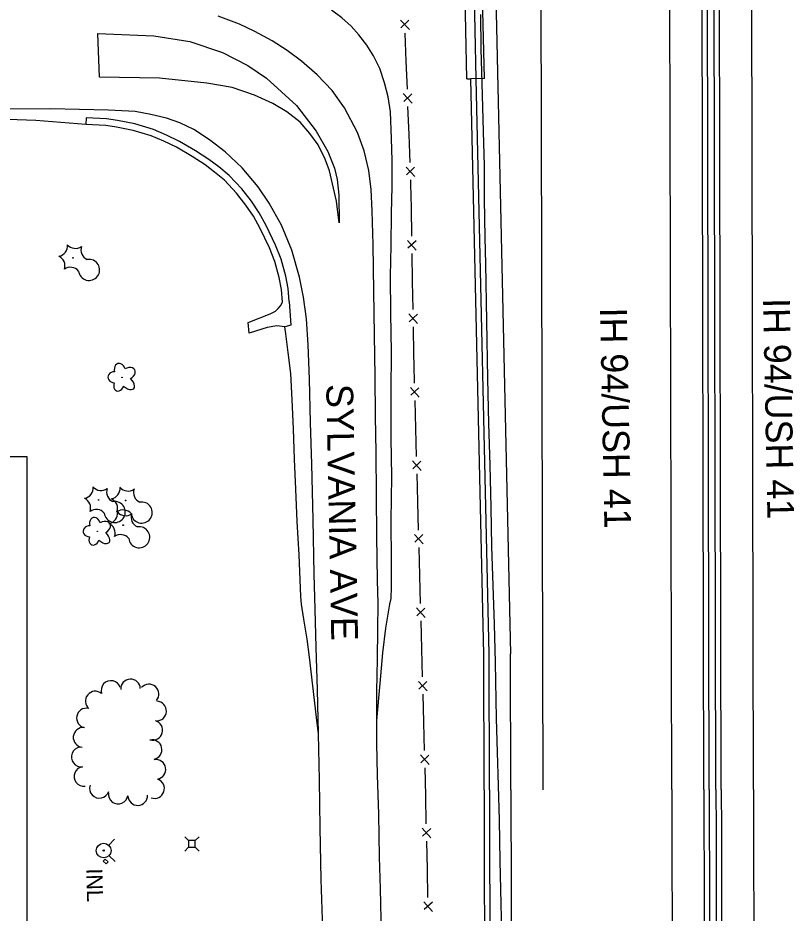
# Model space of a CAD drawing. Extents: x 588843 to 2552415, y 180129 to 269402.
# Drawn here: x 593759.6 to 594049.2, y 183657 to 183991.2 of the extents above; entities that cross this region are included whole.
import ezdxf

# ---------------------------------------------------------------- set-up
doc = ezdxf.new("R2010")
doc.units = 0
for name, color, linetype in [('Default', 7, 'Continuous'), ('E_BLD', 7, 'Continuous'), ('E_DRN', 7, 'Continuous'), ('E_DRN_Text', 7, 'Continuous'), ('E_FEN_P', 7, 'Continuous'), ('E_LAND_TreeLine_P', 7, 'Continuous'), ('E_LAND_Vegetation', 7, 'Continuous'), ('E_RDWY', 7, 'Continuous'), ('E_RDWY_C_and_G', 7, 'Continuous'), ('E_RDWY_Gravel', 7, 'Continuous'), ('E_RDWY_Text', 7, 'Continuous'), ('E_UTL_AG_Bold', 7, 'Continuous'), ('E_UTL_WHydrant', 7, 'Continuous'), ('P_BMGRD', 7, 'Continuous'), ('P_RDWY_BarrierConc', 7, 'Continuous'), ('P_RDWY_PavtEdge', 7, 'Continuous'), ('P_RDWY_ShldPaved', 7, 'Continuous')]:
    doc.layers.add(name, color=color, linetype=linetype)

# ---------------------------------------------------------------- blocks, each defined once
blk = doc.blocks.new('CTRE')
at = {"layer": 'Default'}
blk.add_circle((0, 0), 0.223, dxfattribs=at)
for centre, start, end in [((-11.97, 8.96), 280.2067, 5.97162), ((1.81, 14.92), 220.21132, 305.97623), ((13.83, 5.89), 160.21133, 245.97624), ((-13.83, -5.9), 340.21132, 65.97623), ((12.03, -9.04), 185.92721, 100.25111), ((-1.81, -14.93), 40.21133, 125.97624)]:
    blk.add_arc(centre, 7.87, start, end, dxfattribs=at)
blk = doc.blocks.new('DTRE')
at = {"layer": 'Default'}
blk.add_circle((-0.18, 0), 0.183, dxfattribs=at)
for centre, major_axis, ratio in [((-1.87, 5.32), (1.36, -4.98), 0.782863), ((4.06, 2.74), (-5.27, -2.93), 0.691916), ((-5.87, 0.15), (4.93, -0.12), 0.832022), ((-2.49, -5.24), (1.8, 4.86), 0.716896), ((3.54, -3.71), (-5.01, 4.58), 0.560249)]:
    blk.add_ellipse(centre, major_axis=major_axis, ratio=ratio, start_param=1.570796, end_param=4.712389, dxfattribs=at)
blk = doc.blocks.new('PED')
at = {"layer": 'Default'}
for p, q in [((-2.5, 2.5), (-5.33, 5.33)), ((2.5, 2.5), (5.33, 5.33)), ((-2.5, -2.5), (-5.33, -5.33)), ((2.5, -2.5), (5.33, -5.33))]:
    blk.add_line(p, q, dxfattribs=at)
blk.add_lwpolyline([(-2.5, -2.5), (2.5, -2.5), (2.5, 2.5), (-2.5, 2.5)], close=True, dxfattribs=at)
blk = doc.blocks.new('HYD')
at = {"layer": 'Default'}
for p, q in [((-3.84, 3.84), (-8.32, 8.32)), ((3.84, 3.84), (8.32, 8.32))]:
    blk.add_line(p, q, dxfattribs=at)
for radius in [5.48, 0.42]:
    blk.add_circle((0, 0), radius, dxfattribs=at)
blk = doc.blocks.new('INLT_16')
at = {"layer": 'E_DRN_Text'}
blk.add_text('INL', height=12, dxfattribs=at).set_placement((-11.03, -6))

msp = doc.modelspace()

# ---------------------------------------------------------------- linework, layer by layer
at = {"layer": 'E_BLD'}
msp.add_lwpolyline([(593311.69, 183744.82), (593311.69, 183827.47), (593762.9, 183827.49), (593762.91, 183586.04), (593741.5, 183586.04)], dxfattribs=at)
at = {"layer": 'E_DRN'}
msp.add_lwpolyline([(593792.54, 183675.37), (593791.43, 183676.4), (593792.17, 183677.2), (593793.28, 183676.16), (593792.54, 183675.37)], close=True, dxfattribs=at)
at = {"layer": 'E_FEN_P'}
for p, q in [((593902.32, 183990.35), (593905.64, 183986.82)), ((593905.51, 183990.3), (593902.5, 183987.44)), ((593903.36, 183962.93), (593906.68, 183959.4)), ((593906.54, 183962.88), (593903.54, 183960.02)), ((593904.4, 183935.51), (593907.71, 183931.98)), ((593907.58, 183935.46), (593904.58, 183932.6)), ((593905, 183908.1), (593908.24, 183904.51)), ((593908.18, 183907.99), (593905.12, 183905.19)), ((593905.48, 183880.67), (593908.72, 183877.07)), ((593908.66, 183880.56), (593905.59, 183877.76)), ((593906.03, 183853.22), (593909.31, 183849.66)), ((593909.22, 183853.14), (593906.18, 183850.31)), ((593906.78, 183825.79), (593910.06, 183822.23)), ((593909.96, 183825.71), (593906.93, 183822.88)), ((593907.53, 183798.36), (593910.8, 183794.8)), ((593910.71, 183798.28), (593907.67, 183795.45)), ((593908.28, 183770.93), (593911.55, 183767.37)), ((593911.46, 183770.85), (593908.42, 183768.02)), ((593909.02, 183743.5), (593912.29, 183739.94)), ((593912.2, 183743.42), (593909.16, 183740.59)), ((593909.76, 183716.07), (593913.04, 183712.51)), ((593912.94, 183715.99), (593909.91, 183713.16)), ((593910.42, 183688.65), (593913.68, 183685.07)), ((593913.6, 183688.55), (593910.55, 183685.74)), ((593911.04, 183661.21), (593914.3, 183657.64)), ((593914.22, 183661.12), (593911.17, 183658.3))]:
    msp.add_line(p, q, dxfattribs=at)
for points in [[(593903.98, 183985.53), (593904.37, 183975.06)], [(593904.37, 183975.06), (593904.77, 183964.59)], [(593905.01, 183958.11), (593905.41, 183947.64)], [(593905.41, 183947.64), (593905.81, 183937.17)], [(593906.05, 183930.69), (593906.11, 183929.2), (593906.26, 183920.22)], [(593906.26, 183920.22), (593906.44, 183909.74)], [(593906.55, 183903.26), (593906.74, 183892.78)], [(593906.74, 183892.78), (593906.92, 183882.31)], [(593907.03, 183875.82), (593907.21, 183865.35)], [(593907.21, 183865.35), (593907.27, 183861.79), (593907.46, 183854.87)], [(593907.63, 183848.39), (593907.92, 183837.92)], [(593907.92, 183837.92), (593908.2, 183827.44)], [(593908.38, 183820.96), (593908.67, 183810.49)], [(593908.67, 183810.49), (593908.95, 183800.01)], [(593909.13, 183793.53), (593909.41, 183783.06)], [(593909.41, 183783.06), (593909.7, 183772.58)], [(593909.88, 183766.1), (593910.16, 183755.63)], [(593910.16, 183755.63), (593910.44, 183745.15)], [(593910.62, 183738.67), (593910.9, 183728.2)], [(593910.9, 183728.2), (593911.19, 183717.72)], [(593911.36, 183711.24), (593911.5, 183706.07), (593911.62, 183700.77)], [(593911.62, 183700.77), (593911.85, 183690.29)], [(593912, 183683.81), (593912.24, 183673.33)], [(593912.24, 183673.33), (593912.47, 183662.86)]]:
    msp.add_lwpolyline(points, dxfattribs=at)
at = {"layer": 'E_LAND_TreeLine_P'}
for centre, start, end in [((593794.32, 183740.07), 17.8701, 197.8701), ((593801.61, 183740.68), 2.2989, 182.2989), ((593808.54, 183738.78), 318.9547, 138.9547), ((593788.45, 183736.15), 50.2231, 230.2231), ((593811.33, 183732.41), 267.4816, 87.4816), ((593785.17, 183729.83), 78.7085, 258.7085), ((593809.92, 183725.24), 254.2754, 74.2754), ((593783.92, 183722.6), 84.4268, 264.4268), ((593783.24, 183715.29), 97.4501, 277.4501), ((593809.66, 183718.01), 283.0149, 103.0149), ((593811.1, 183710.66), 279.5734, 99.5734), ((593784.2, 183708.01), 97.4501, 277.4501), ((593810.58, 183703.49), 250.7284, 70.7284), ((593790, 183703.58), 161.9581, 341.9581), ((593797, 183701.4), 172.7858, 352.7858), ((593804.31, 183700.9), 182.1033, 2.1033)]:
    msp.add_arc(centre, 3.67, start, end, dxfattribs=at)
at = {"layer": 'E_RDWY'}
for points in [[(593895.2, 183649.15), (593894.83, 183666.12), (593894.47, 183677.96), (593894.2, 183693.95), (593893.72, 183708.52), (593893.47, 183720.33), (593893.45, 183728.95), (593893.5, 183739.8), (593893.7, 183751.8), (593893.88, 183762.88), (593893.95, 183772.58), (593893.8, 183781.3), (593893.54, 183797.62), (593893.42, 183813.02), (593893.24, 183828.99), (593893.04, 183842.53), (593892.84, 183857.3), (593892.65, 183872.83), (593892.41, 183889.21), (593892.1, 183906.41), (593891.82, 183919.13), (593891.44, 183927.1), (593890.54, 183934.24), (593888.74, 183941.52), (593886.32, 183948.45), (593881.46, 183957.65), (593876.82, 183964.09), (593871.2, 183969.97), (593865.42, 183975.07), (593860.1, 183979.02), (593854.44, 183982.65), (593848.03, 183986.06), (593842.29, 183988.79), (593834.34, 183991.79)], [(593873.41, 183650.87), (593872.77, 183669.49), (593872.39, 183688.88), (593872.11, 183706.78), (593871.79, 183723.91), (593871.37, 183740.42), (593870.92, 183756.17), (593870.52, 183770.46), (593870.17, 183783.59), (593869.71, 183803.92), (593869.21, 183824.65), (593868.78, 183840.15), (593868.41, 183856.3), (593867.88, 183869.15), (593867.22, 183878.82), (593866.17, 183886.9), (593864.68, 183894.41), (593861.76, 183904.45), (593857.91, 183913.83), (593853.3, 183922.05), (593849.25, 183928.08), (593843.25, 183935.25), (593836.98, 183941.2), (593831.09, 183945.64), (593825.23, 183949.46), (593820.06, 183952.06), (593815.09, 183953.78), (593809.21, 183955.12), (593803.29, 183956.18), (593793.36, 183956.79), (593771.72, 183957.24), (593753.34, 183957.17)], [(593860.85, 183885.32), (593860.42, 183890.15), (593859.57, 183894.8), (593857.78, 183901.07), (593855.74, 183906.39), (593852.19, 183913.67), (593849.6, 183918.42), (593846.69, 183922.75), (593843.11, 183927.41), (593838.45, 183932.38), (593834.55, 183935.58), (593830.84, 183938.36), (593825.89, 183941.58), (593819.94, 183945.09), (593815.07, 183947.46), (593810.15, 183949.46), (593803.21, 183951.59), (593796.82, 183952.9), (593792.64, 183953.46), (593785.03, 183953.83)], [(593858.36, 183885.1), (593857.94, 183889.82), (593857.13, 183894.23), (593855.4, 183900.27), (593853.44, 183905.39), (593849.96, 183912.52), (593847.46, 183917.12), (593844.66, 183921.29), (593841.2, 183925.79), (593836.73, 183930.55), (593833.01, 183933.61), (593829.41, 183936.31), (593824.57, 183939.45), (593818.76, 183942.88), (593814.05, 183945.17), (593809.31, 183947.1), (593802.59, 183949.17), (593796.41, 183950.43), (593792.41, 183950.96), (593784.91, 183951.33)], [(593860.85, 183885.32), (593861.47, 183876.45), (593859.16, 183875.86), (593856.2, 183876.29), (593852.59, 183875.67), (593845.85, 183873.44), (593845.49, 183877.53), (593853.71, 183880.7), (593855.69, 183881.73), (593856.64, 183882.7), (593857.53, 183883.67), (593858.36, 183885.1)]]:
    msp.add_lwpolyline(points, dxfattribs=at)
msp.add_lwpolyline([(593879.52, 183914.66), (593878.48, 183922.74), (593875.91, 183934.13), (593874.26, 183938.46), (593871.62, 183943.8), (593868.57, 183948.01), (593864.88, 183952.22), (593859.94, 183956.13), (593854.76, 183959.17), (593847.91, 183962.32), (593839.48, 183965.2), (593830.1, 183966.86), (593812.38, 183968.65), (593790.08, 183969.02), (593789.43, 183985.36), (593810.37, 183984.46), (593823.72, 183982.41), (593835.93, 183978.25), (593845.34, 183973.39), (593852.41, 183968.71), (593863.51, 183958.46), (593870.87, 183948.9), (593875.17, 183941.3), (593877.76, 183935.06), (593878.74, 183930.86), (593879.34, 183924.99), (593879.52, 183914.66)], close=True, dxfattribs=at)
at = {"layer": 'E_RDWY_C_and_G'}
msp.add_line((593785.03, 183953.83), (593784.91, 183951.33), dxfattribs=at)
at = {"layer": 'E_RDWY_Gravel'}
for points in [[(593893.45, 183728.95), (593894.75, 183742.76), (593895.8, 183754.16), (593896.85, 183763.31), (593898.41, 183772.3), (593898.86, 183774.44), (593898.95, 183778.72), (593898.99, 183788.32), (593898.88, 183803.61), (593899.05, 183820.01), (593898.91, 183834.27), (593898.9, 183851.73), (593898.94, 183866.36), (593898.75, 183880.98), (593898.65, 183894.8), (593898.85, 183906.23), (593898.93, 183918.17), (593899.18, 183928.25), (593899.2, 183938), (593899, 183946.15), (593898.63, 183956.16), (593897.73, 183961.73), (593896.41, 183967), (593894.68, 183972.34), (593892.27, 183977), (593889.79, 183981.05), (593886.84, 183984.88), (593883.96, 183988.09), (593880.42, 183991.15), (593876.61, 183994.08)], [(593932.13, 183992.46), (593932.33, 183979.66), (593932.71, 183966.87), (593933.15, 183948.79), (593933.51, 183936), (593933.61, 183923.46), (593933.83, 183909.18), (593934.07, 183899.32), (593934.84, 183856.51), (593935.21, 183839.74), (593935.61, 183824.27), (593935.98, 183808.46), (593936.35, 183793.91), (593936.81, 183779.34), (593937.23, 183764.82), (593937.66, 183750.53), (593938.06, 183729.66), (593938.42, 183717.08), (593938.78, 183704.67), (593939.16, 183691.67), (593939.43, 183676.56), (593939.8, 183660.46), (593940.15, 183644.83)], [(593784.91, 183951.33), (593775.68, 183952.17), (593766.25, 183952.93), (593755.86, 183953.21)], [(593871.79, 183723.91), (593870.94, 183730), (593869.6, 183741.87), (593868.43, 183752.52), (593867.46, 183759.26), (593866.22, 183766.74), (593865.45, 183772.29), (593865.13, 183775.15), (593864.5, 183790.73), (593863.73, 183803.25), (593863.29, 183815.27), (593862.84, 183826.49), (593862.4, 183837.78), (593861.96, 183848.59), (593861.38, 183858.39), (593860.46, 183866.29), (593859.56, 183873.28), (593859.16, 183875.86)]]:
    msp.add_lwpolyline(points, dxfattribs=at)
at = {"layer": 'P_BMGRD'}
for p, q in [((593930.23, 183986.62), (593929.67, 184011.61)), ((593930.63, 183968.47), (593930.23, 183986.62))]:
    msp.add_line(p, q, dxfattribs=at)
at = {"layer": 'P_RDWY_BarrierConc'}
for p, q in [((594015.52, 183703.15), (594011.71, 185400.89)), ((594017.52, 183703.15), (594013.71, 185400.03)), ((594020.02, 183703.16), (594016.21, 185398.95)), ((594022.02, 183703.16), (594018.21, 185398.08)), ((593933.63, 183968.54), (593928.63, 183968.43)), ((593933.41, 183753.59), (593928.63, 183968.43)), ((593935.41, 183753.64), (593930.63, 183968.47)), ((593933.52, 183702.97), (593933.41, 183753.79)), ((593935.52, 183702.97), (593935.41, 183753.8))]:
    msp.add_line(p, q, dxfattribs=at)
for radius, end in [(171966.59, 180.2118368), (171964.59, 180.2118368), (171884.59, 180.4530652), (171882.59, 180.4530652), (171880.09, 180.4530652), (171878.09, 180.4530652)]:
    msp.add_arc((765899.68, 184089.33), radius, 180.1287302, end, dxfattribs=at)
at = {"layer": 'P_RDWY_PavtEdge'}
for p, q in [((594003.52, 183703.12), (593999.78, 185371.14)), ((594034.02, 183703.19), (594030.35, 185336.23)), ((593955.52, 183703.01), (593953.77, 184483.94)), ((593936.73, 184053.8), (593943.41, 183753.81)), ((593926.73, 183986.54), (593926.17, 184011.53)), ((593927.13, 183968.4), (593926.73, 183986.54)), ((593927.13, 183968.4), (593928.63, 183968.43)), ((593943.52, 183702.99), (593943.41, 183753.81))]:
    msp.add_line(p, q, dxfattribs=at)
for radius, end in [(171956.59, 180.211791), (171896.59, 180.4530652), (171866.09, 180.4530652)]:
    msp.add_arc((765899.68, 184089.33), radius, 180.1287302, end, dxfattribs=at)
at = {"layer": 'P_RDWY_ShldPaved'}
msp.add_line((593933.63, 183968.54), (593931.74, 184053.69), dxfattribs=at)

# ---------------------------------------------------------------- block references
at = {"layer": 'E_DRN_Text', "xscale": 0.5, "yscale": 0.5000000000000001, "rotation": -88.48617554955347}
msp.add_blockref('INLT_16', (593788.24, 183668.19), dxfattribs=at)
at = {"layer": 'E_LAND_Vegetation', "xscale": 0.5, "yscale": 0.5, "rotation": 0.06972781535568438}
for name, p in [('CTRE', (593780.14, 183901.61)), ('DTRE', (593798.56, 183856.96)), ('CTRE', (593789.72, 183811.24)), ('CTRE', (593799.77, 183811.04)), ('CTRE', (593798.86, 183801.82)), ('DTRE', (593789.32, 183799.49))]:
    msp.add_blockref(name, p, dxfattribs=at)
at = {"layer": 'E_UTL_AG_Bold', "xscale": 0.5, "yscale": 0.5, "rotation": 0.06972781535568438}
msp.add_blockref('PED', (593824.51, 183682.83), dxfattribs=at)
at = {"layer": 'E_UTL_WHydrant', "xscale": 0.5, "yscale": 0.5000000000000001, "rotation": -88.48617554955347}
msp.add_blockref('HYD', (593791.6, 183680.36), dxfattribs=at)

# ---------------------------------------------------------------- texts
at = {"layer": 'E_RDWY_Text'}
for s, p in [('IH 94/USH 41', (594037.6, 183886.48)), ('IH 94/USH 41', (593976.78, 183882.94)), ('SYLVANIA AVE', (593874.62, 183854.43))]:
    msp.add_text(s, height=10, rotation=271.1407, dxfattribs=at).set_placement(p)

doc.saveas('drawing.dxf')
